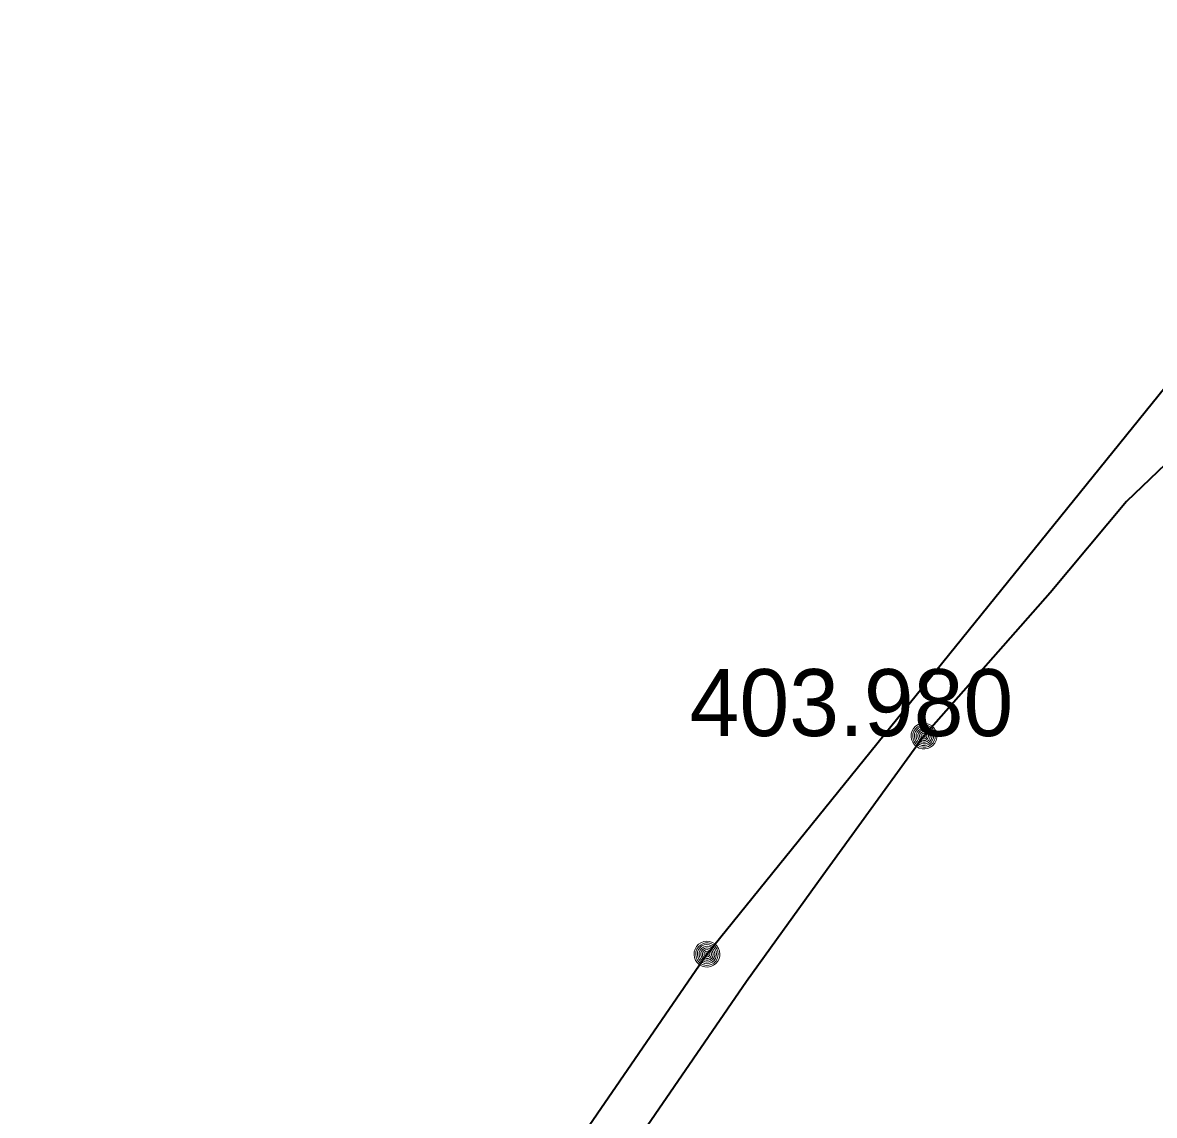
# Model space of a CAD drawing. Extents: x -873619 to -867639, y -1015082 to -1012326.
# Drawn here: x -868007.52 to -867987.24, y -1012720.88 to -1012701.3 of the extents above; entities that cross this region are included whole.
import ezdxf

# ---------------------------------------------------------------- set-up
doc = ezdxf.new("R2010")
doc.units = 0
doc.header["$LTSCALE"] = 0.44
for name, color, linetype, lineweight in [('1', 7, 'Continuous', 13), ('21', 7, 'Continuous', 35), ('25', 7, 'Continuous', 13)]:
    doc.layers.add(name, color=color, linetype=linetype, lineweight=lineweight)

msp = doc.modelspace()

# ---------------------------------------------------------------- linework, layer by layer
at = {"layer": '1'}
for points in [[(-867991.137, -1012714.083), (-867991.144, -1012714.031), (-867991.161, -1012713.981), (-867991.19, -1012713.937), (-867991.227, -1012713.9), (-867991.272, -1012713.873), (-867991.321, -1012713.856), (-867991.375, -1012713.852), (-867991.426, -1012713.859), (-867991.475, -1012713.878), (-867991.519, -1012713.907), (-867991.554, -1012713.946), (-867991.581, -1012713.991), (-867991.597, -1012714.042), (-867991.6, -1012714.094), (-867991.592, -1012714.146), (-867991.571, -1012714.195), (-867991.541, -1012714.238), (-867991.502, -1012714.272), (-867991.456, -1012714.298), (-867991.404, -1012714.312), (-867991.352, -1012714.314), (-867991.301, -1012714.304), (-867991.252, -1012714.283), (-867991.21, -1012714.252), (-867991.176, -1012714.211), (-867991.152, -1012714.165), (-867991.139, -1012714.114)], [(-867991.168, -1012714.083), (-867991.174, -1012714.034), (-867991.191, -1012713.988), (-867991.218, -1012713.948), (-867991.255, -1012713.916), (-867991.299, -1012713.894), (-867991.348, -1012713.883), (-867991.397, -1012713.883), (-867991.443, -1012713.896), (-867991.487, -1012713.92), (-867991.522, -1012713.953), (-867991.549, -1012713.994), (-867991.566, -1012714.041), (-867991.57, -1012714.09), (-867991.563, -1012714.138), (-867991.544, -1012714.183), (-867991.514, -1012714.223), (-867991.475, -1012714.254), (-867991.431, -1012714.274), (-867991.384, -1012714.284), (-867991.335, -1012714.282), (-867991.288, -1012714.267), (-867991.245, -1012714.242), (-867991.21, -1012714.208), (-867991.184, -1012714.166), (-867991.171, -1012714.119)], [(-867991.198, -1012714.083), (-867991.203, -1012714.038), (-867991.22, -1012713.996), (-867991.249, -1012713.961), (-867991.284, -1012713.934), (-867991.326, -1012713.917), (-867991.372, -1012713.912), (-867991.416, -1012713.918), (-867991.458, -1012713.937), (-867991.492, -1012713.965), (-867991.519, -1012714.002), (-867991.536, -1012714.044), (-867991.539, -1012714.089), (-867991.532, -1012714.134), (-867991.514, -1012714.175), (-867991.485, -1012714.209), (-867991.448, -1012714.235), (-867991.404, -1012714.251), (-867991.36, -1012714.254), (-867991.315, -1012714.246), (-867991.274, -1012714.226), (-867991.24, -1012714.197), (-867991.215, -1012714.159), (-867991.201, -1012714.116)], [(-867991.228, -1012714.083), (-867991.232, -1012714.042), (-867991.25, -1012714.005), (-867991.277, -1012713.974), (-867991.313, -1012713.953), (-867991.353, -1012713.942), (-867991.394, -1012713.944), (-867991.433, -1012713.957), (-867991.467, -1012713.981), (-867991.492, -1012714.013), (-867991.507, -1012714.051), (-867991.509, -1012714.092), (-867991.502, -1012714.132), (-867991.482, -1012714.168), (-867991.453, -1012714.197), (-867991.416, -1012714.216), (-867991.375, -1012714.224), (-867991.335, -1012714.22), (-867991.296, -1012714.205), (-867991.264, -1012714.179), (-867991.242, -1012714.145), (-867991.228, -1012714.106)], [(-867991.257, -1012714.083), (-867991.262, -1012714.047), (-867991.281, -1012714.015), (-867991.306, -1012713.99), (-867991.34, -1012713.975), (-867991.377, -1012713.972), (-867991.411, -1012713.98), (-867991.443, -1012714), (-867991.465, -1012714.028), (-867991.478, -1012714.062), (-867991.478, -1012714.099), (-867991.468, -1012714.134), (-867991.446, -1012714.163), (-867991.416, -1012714.184), (-867991.382, -1012714.194), (-867991.345, -1012714.192), (-867991.311, -1012714.178), (-867991.284, -1012714.155), (-867991.264, -1012714.123), (-867991.257, -1012714.088)], [(-867991.288, -1012714.083), (-867991.293, -1012714.052), (-867991.309, -1012714.026), (-867991.335, -1012714.009), (-867991.365, -1012714.002), (-867991.397, -1012714.006), (-867991.424, -1012714.023), (-867991.441, -1012714.047), (-867991.45, -1012714.078), (-867991.446, -1012714.108), (-867991.431, -1012714.136), (-867991.406, -1012714.155), (-867991.377, -1012714.164), (-867991.345, -1012714.161), (-867991.318, -1012714.147), (-867991.298, -1012714.123), (-867991.288, -1012714.094)], [(-867991.318, -1012714.083), (-867991.323, -1012714.059), (-867991.34, -1012714.041), (-867991.362, -1012714.032), (-867991.387, -1012714.035), (-867991.407, -1012714.049), (-867991.419, -1012714.071), (-867991.419, -1012714.096), (-867991.406, -1012714.117), (-867991.387, -1012714.131), (-867991.362, -1012714.134), (-867991.338, -1012714.125), (-867991.323, -1012714.107)], [(-867991.348, -1012714.083), (-867991.353, -1012714.068), (-867991.367, -1012714.062), (-867991.382, -1012714.066), (-867991.389, -1012714.08), (-867991.386, -1012714.095), (-867991.372, -1012714.104), (-867991.357, -1012714.101), (-867991.348, -1012714.089)]]:
    msp.add_lwpolyline(points, close=True, dxfattribs=at)
at = {"layer": '21'}
for points in [[(-868007.52, -1012735.85), (-867995.258, -1012717.991), (-867981.769, -1012701.297)], [(-867986.903, -1012709.08), (-867987.741, -1012709.882), (-867989.108, -1012711.515), (-867991.369, -1012714.083), (-867993.183, -1012716.581), (-867994.551, -1012718.479), (-867999.799, -1012726.127)]]:
    msp.add_lwpolyline(points, dxfattribs=at)
at = {"layer": '25'}
for points in [[(-867995.027, -1012717.991), (-867995.033, -1012717.939), (-867995.05, -1012717.889), (-867995.079, -1012717.845), (-867995.116, -1012717.808), (-867995.161, -1012717.781), (-867995.211, -1012717.764), (-867995.264, -1012717.76), (-867995.316, -1012717.767), (-867995.365, -1012717.786), (-867995.408, -1012717.815), (-867995.444, -1012717.854), (-867995.47, -1012717.899), (-867995.486, -1012717.95), (-867995.489, -1012718.002), (-867995.481, -1012718.054), (-867995.461, -1012718.103), (-867995.43, -1012718.146), (-867995.391, -1012718.18), (-867995.345, -1012718.206), (-867995.294, -1012718.22), (-867995.241, -1012718.222), (-867995.19, -1012718.212), (-867995.142, -1012718.191), (-867995.099, -1012718.16), (-867995.065, -1012718.119), (-867995.041, -1012718.073), (-867995.029, -1012718.022)], [(-867995.057, -1012717.991), (-867995.063, -1012717.942), (-867995.08, -1012717.896), (-867995.108, -1012717.856), (-867995.145, -1012717.824), (-867995.189, -1012717.802), (-867995.237, -1012717.791), (-867995.286, -1012717.791), (-867995.333, -1012717.804), (-867995.376, -1012717.828), (-867995.412, -1012717.861), (-867995.439, -1012717.902), (-867995.455, -1012717.949), (-867995.459, -1012717.998), (-867995.452, -1012718.046), (-867995.433, -1012718.091), (-867995.403, -1012718.131), (-867995.365, -1012718.162), (-867995.321, -1012718.182), (-867995.273, -1012718.192), (-867995.224, -1012718.19), (-867995.177, -1012718.175), (-867995.134, -1012718.15), (-867995.1, -1012718.116), (-867995.074, -1012718.074), (-867995.06, -1012718.027)], [(-867995.087, -1012717.991), (-867995.093, -1012717.946), (-867995.11, -1012717.904), (-867995.138, -1012717.869), (-867995.174, -1012717.842), (-867995.216, -1012717.825), (-867995.261, -1012717.82), (-867995.306, -1012717.826), (-867995.347, -1012717.845), (-867995.382, -1012717.873), (-867995.409, -1012717.91), (-867995.425, -1012717.952), (-867995.429, -1012717.997), (-867995.422, -1012718.042), (-867995.403, -1012718.083), (-867995.374, -1012718.117), (-867995.337, -1012718.143), (-867995.294, -1012718.159), (-867995.249, -1012718.162), (-867995.204, -1012718.154), (-867995.164, -1012718.134), (-867995.13, -1012718.105), (-867995.104, -1012718.067), (-867995.09, -1012718.024)], [(-867995.117, -1012717.991), (-867995.122, -1012717.95), (-867995.14, -1012717.913), (-867995.167, -1012717.882), (-867995.202, -1012717.861), (-867995.242, -1012717.85), (-867995.283, -1012717.852), (-867995.322, -1012717.865), (-867995.356, -1012717.889), (-867995.381, -1012717.921), (-867995.396, -1012717.959), (-867995.399, -1012718), (-867995.391, -1012718.04), (-867995.371, -1012718.076), (-867995.342, -1012718.105), (-867995.305, -1012718.124), (-867995.265, -1012718.132), (-867995.224, -1012718.128), (-867995.186, -1012718.113), (-867995.154, -1012718.087), (-867995.131, -1012718.053), (-867995.118, -1012718.014)], [(-867995.147, -1012717.991), (-867995.152, -1012717.955), (-867995.17, -1012717.923), (-867995.196, -1012717.898), (-867995.23, -1012717.883), (-867995.266, -1012717.88), (-867995.301, -1012717.888), (-867995.332, -1012717.908), (-867995.355, -1012717.936), (-867995.368, -1012717.97), (-867995.368, -1012718.007), (-867995.357, -1012718.042), (-867995.336, -1012718.071), (-867995.306, -1012718.092), (-867995.271, -1012718.102), (-867995.234, -1012718.1), (-867995.2, -1012718.086), (-867995.173, -1012718.063), (-867995.154, -1012718.031), (-867995.147, -1012717.996)], [(-867995.177, -1012717.991), (-867995.182, -1012717.96), (-867995.199, -1012717.934), (-867995.225, -1012717.917), (-867995.255, -1012717.91), (-867995.286, -1012717.914), (-867995.313, -1012717.931), (-867995.331, -1012717.955), (-867995.339, -1012717.986), (-867995.335, -1012718.016), (-867995.32, -1012718.044), (-867995.296, -1012718.063), (-867995.266, -1012718.072), (-867995.235, -1012718.069), (-867995.207, -1012718.055), (-867995.187, -1012718.031), (-867995.177, -1012718.002)], [(-867995.207, -1012717.991), (-867995.212, -1012717.967), (-867995.229, -1012717.949), (-867995.252, -1012717.94), (-867995.276, -1012717.943), (-867995.297, -1012717.957), (-867995.308, -1012717.979), (-867995.308, -1012718.004), (-867995.296, -1012718.025), (-867995.276, -1012718.039), (-867995.251, -1012718.042), (-867995.228, -1012718.033), (-867995.212, -1012718.015)], [(-867995.237, -1012717.991), (-867995.242, -1012717.976), (-867995.257, -1012717.97), (-867995.272, -1012717.974), (-867995.279, -1012717.988), (-867995.275, -1012718.003), (-867995.262, -1012718.012), (-867995.247, -1012718.009), (-867995.237, -1012717.997)]]:
    msp.add_lwpolyline(points, close=True, dxfattribs=at)

# ---------------------------------------------------------------- texts
at = {"layer": '1'}
msp.add_text('403.980 ', height=1.2, dxfattribs=at).set_placement((-867995.569, -1012714.083))

doc.saveas('drawing.dxf')
